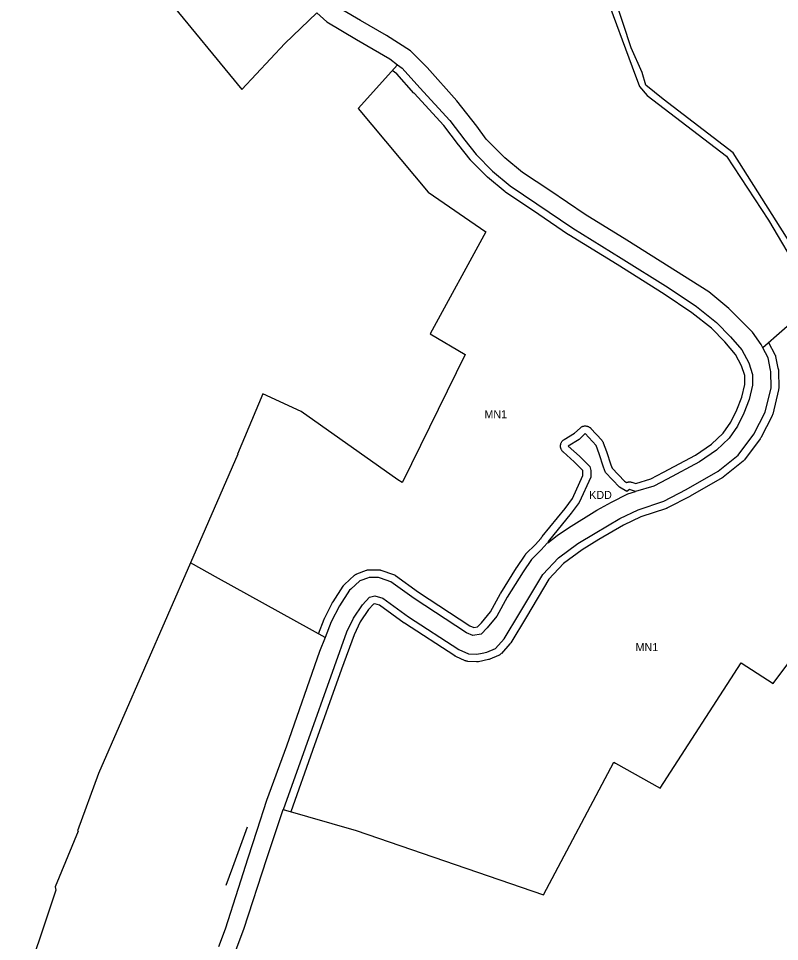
# Model space of a CAD drawing. Extents: x 7435758 to 7439981, y 5550649 to 5554049.
# Drawn here: x 7439239 to 7439733, y 5552845 to 5553445 of the extents above; entities that cross this region are included whole.
import ezdxf

# ---------------------------------------------------------------- set-up
doc = ezdxf.new("R2010")
doc.units = 0
for name, color, linetype in [('linie_rozgraniczające', 7, 'Continuous'), ('linie_zabudowy_nieprzekraczalne', 7, 'Continuous'), ('oznaczenia_przeznaczen', 7, 'Continuous')]:
    doc.layers.add(name, color=color, linetype=linetype)

msp = doc.modelspace()

# ---------------------------------------------------------------- linework, layer by layer
at = {"layer": 'linie_rozgraniczające'}
for p, q in [((7439600.88, 5553512.3), (7439637.66, 5553413.68)), ((7439301.05, 5553499.96), (7439384, 5553398.96)), ((7439636.99, 5553425.88), (7439626.65, 5553457.88)), ((7439411.84, 5553428.79), (7439432.82, 5553448.74)), ((7439432.82, 5553448.74), (7439439.32, 5553442.88)), ((7439461.17, 5553443.77), (7439449.57, 5553450.46)), ((7439439.32, 5553442.88), (7439458.54, 5553431.42)), ((7439477.97, 5553434.03), (7439461.17, 5553443.77)), ((7439384, 5553398.96), (7439411.84, 5553428.79)), ((7439458.54, 5553431.42), (7439480.15, 5553418.75)), ((7439493.49, 5553423.98), (7439477.97, 5553434.03)), ((7439504.34, 5553413.22), (7439493.49, 5553423.98)), ((7439644.02, 5553409.86), (7439636.99, 5553425.88)), ((7439480.15, 5553418.75), (7439485.04, 5553415.02)), ((7439485.04, 5553415.02), (7439459.63, 5553386.44)), ((7439485.04, 5553415.02), (7439488.08, 5553412.69)), ((7439488.08, 5553412.69), (7439499.54, 5553399.88)), ((7439523.71, 5553391.61), (7439504.34, 5553413.22)), ((7439637.66, 5553413.68), (7439642.44, 5553400.76)), ((7439646.47, 5553401.81), (7439644.02, 5553409.86)), ((7439499.54, 5553399.88), (7439519.15, 5553378.79)), ((7439642.44, 5553400.76), (7439647.28, 5553394.93)), ((7439657.82, 5553392.7), (7439646.47, 5553401.81)), ((7439647.28, 5553394.93), (7439698.84, 5553355.57)), ((7439703.19, 5553357.69), (7439657.82, 5553392.7)), ((7439536.75, 5553375.08), (7439523.71, 5553391.61)), ((7439459.63, 5553386.44), (7439505.06, 5553332.29)), ((7439519.15, 5553378.79), (7439528.79, 5553365.9)), ((7439542.82, 5553366.73), (7439536.75, 5553375.08)), ((7439528.79, 5553365.9), (7439536.2, 5553356.56)), ((7439554.78, 5553354.45), (7439542.82, 5553366.73)), ((7439748.06, 5553286.69), (7439703.19, 5553357.69)), ((7439536.2, 5553356.56), (7439546.8, 5553345.79)), ((7439566.36, 5553345.02), (7439554.78, 5553354.45)), ((7439698.84, 5553355.57), (7439726.22, 5553313.97)), ((7439546.8, 5553345.79), (7439558.26, 5553336.23)), ((7439584.03, 5553333.24), (7439566.36, 5553345.02)), ((7439558.26, 5553336.23), (7439575.65, 5553324.69)), ((7439607.06, 5553317.76), (7439584.03, 5553333.24)), ((7439505.06, 5553332.29), (7439542.61, 5553306.52)), ((7439575.65, 5553324.69), (7439598.96, 5553308.71)), ((7439634.18, 5553301.02), (7439607.06, 5553317.76)), ((7439598.96, 5553308.71), (7439630.48, 5553289.41)), ((7439726.22, 5553313.97), (7439757.05, 5553261.56)), ((7439542.61, 5553306.52), (7439506.32, 5553240.2)), ((7439687.37, 5553267.5), (7439634.18, 5553301.02)), ((7439630.48, 5553289.41), (7439661.08, 5553270.21)), ((7439661.08, 5553270.21), (7439679.29, 5553257.92)), ((7439700.31, 5553256.56), (7439687.37, 5553267.5)), ((7439757.05, 5553261.56), (7439722.38, 5553231.16)), ((7439679.29, 5553257.92), (7439692.48, 5553247.52)), ((7439715.78, 5553241.3), (7439700.31, 5553256.56)), ((7439692.48, 5553247.52), (7439701.45, 5553238.25)), ((7439506.32, 5553240.2), (7439529.01, 5553226.77)), ((7439701.45, 5553238.25), (7439708.83, 5553229.69)), ((7439721.32, 5553233.19), (7439715.78, 5553241.3)), ((7439722.38, 5553231.16), (7439721.32, 5553233.19)), ((7439725.84, 5553224.52), (7439722.38, 5553231.16)), ((7439529.01, 5553226.77), (7439488.29, 5553143.79)), ((7439708.83, 5553229.69), (7439713.34, 5553221.28)), ((7439713.34, 5553221.28), (7439715.72, 5553213.82)), ((7439727.46, 5553216.51), (7439725.84, 5553224.52)), ((7439715.72, 5553213.82), (7439715.75, 5553206.79)), ((7439727.74, 5553215.81), (7439727.46, 5553216.51)), ((7439727.8, 5553205.01), (7439727.74, 5553215.81)), ((7439715.75, 5553206.79), (7439713.65, 5553197.46)), ((7439397.71, 5553201.15), (7439381.25, 5553162.1)), ((7439422.48, 5553189.83), (7439397.71, 5553201.15)), ((7439724.05, 5553189.22), (7439727.8, 5553205.01)), ((7439713.65, 5553197.46), (7439710.1, 5553188.72)), ((7439485.25, 5553145.29), (7439422.48, 5553189.83)), ((7439716.67, 5553174.92), (7439724.05, 5553189.22)), ((7439710.1, 5553188.72), (7439706.02, 5553180.22)), ((7439706.02, 5553180.22), (7439700.6, 5553172.44)), ((7439603.12, 5553171.56), (7439596.04, 5553167.28)), ((7439607.13, 5553175.34), (7439603.12, 5553171.56)), ((7439614.15, 5553167.65), (7439607.13, 5553175.34)), ((7439700.6, 5553172.44), (7439692.33, 5553164.56)), ((7439706.52, 5553161.34), (7439716.67, 5553174.92)), ((7439596.04, 5553167.28), (7439603.38, 5553160.69)), ((7439616.19, 5553162.12), (7439614.15, 5553167.65)), ((7439381.35, 5553162.05), (7439350.6, 5553091.47)), ((7439381.25, 5553162.1), (7439381.35, 5553162.05)), ((7439603.38, 5553160.69), (7439610, 5553153.89)), ((7439619.07, 5553153.53), (7439616.19, 5553162.12)), ((7439692.33, 5553164.56), (7439681.43, 5553157.08)), ((7439693.5, 5553150.93), (7439706.52, 5553161.34)), ((7439610, 5553153.89), (7439610.64, 5553151.38)), ((7439620.3, 5553150.14), (7439619.07, 5553153.53)), ((7439681.43, 5553157.08), (7439660.27, 5553145.8)), ((7439610.64, 5553147.03), (7439603.15, 5553130.59)), ((7439610.64, 5553151.38), (7439610.64, 5553147.03)), ((7439629.39, 5553140.54), (7439620.3, 5553150.14)), ((7439672.71, 5553138.98), (7439693.5, 5553150.93)), ((7439488.18, 5553143.57), (7439485.25, 5553145.29)), ((7439488.29, 5553143.79), (7439488.18, 5553143.57)), ((7439651.6, 5553141.28), (7439639.85, 5553137.7)), ((7439660.27, 5553145.8), (7439651.6, 5553141.28)), ((7439624.15, 5553130.79), (7439634.87, 5553136.18)), ((7439634.03, 5553137.83), (7439629.39, 5553140.54)), ((7439635.8, 5553138.99), (7439634.03, 5553137.83)), ((7439634.87, 5553136.18), (7439639.85, 5553137.7)), ((7439639.85, 5553137.7), (7439635.8, 5553138.99)), ((7439658.2, 5553131.53), (7439672.71, 5553138.98)), ((7439603.15, 5553130.59), (7439597.99, 5553123.68)), ((7439614.72, 5553125.72), (7439624.15, 5553130.79)), ((7439641.41, 5553125.91), (7439658.2, 5553131.53)), ((7439597.99, 5553123.68), (7439582.97, 5553105.31)), ((7439596.31, 5553114.17), (7439614.72, 5553125.72)), ((7439629.57, 5553120.21), (7439641.41, 5553125.91)), ((7439613.49, 5553110.78), (7439629.57, 5553120.21)), ((7439588.96, 5553109.18), (7439596.31, 5553114.17)), ((7439582.76, 5553104.51), (7439588.96, 5553109.18)), ((7439582.97, 5553105.31), (7439582.76, 5553104.51)), ((7439602.24, 5553104.01), (7439613.49, 5553110.78)), ((7439578.39, 5553099.9), (7439572.13, 5553093.65)), ((7439582.38, 5553104.23), (7439578.39, 5553099.9)), ((7439582.76, 5553104.51), (7439582.38, 5553104.23)), ((7439589.72, 5553094.72), (7439602.24, 5553104.01)), ((7439572.13, 5553093.65), (7439566.73, 5553085.62)), ((7439579.46, 5553083.88), (7439589.72, 5553094.72)), ((7439350.6, 5553091.47), (7439290.94, 5552954.55)), ((7439368.93, 5553081.28), (7439350.6, 5553091.47)), ((7439438.12, 5553042.85), (7439368.93, 5553081.28)), ((7439465.69, 5553081.56), (7439461.38, 5553079.93)), ((7439466.73, 5553081.95), (7439465.69, 5553081.56)), ((7439469.44, 5553081.94), (7439466.73, 5553081.95)), ((7439472.72, 5553081.93), (7439469.44, 5553081.94)), ((7439474.12, 5553081.46), (7439472.72, 5553081.93)), ((7439480.91, 5553079.14), (7439474.12, 5553081.46)), ((7439566.73, 5553085.62), (7439556.46, 5553069.05)), ((7439564.69, 5553059), (7439579.46, 5553083.88)), ((7439460.57, 5553079.62), (7439454.83, 5553074.35)), ((7439461.38, 5553079.93), (7439460.57, 5553079.62)), ((7439495.94, 5553068.29), (7439480.91, 5553079.14)), ((7439729.26, 5553013.06), (7439776.92, 5553077.3)), ((7439454.05, 5553073.62), (7439447.43, 5553063.46)), ((7439454.83, 5553074.35), (7439454.05, 5553073.62)), ((7439462.4, 5553064.17), (7439466.87, 5553069.02)), ((7439466.87, 5553069.02), (7439470.4, 5553069.99)), ((7439470.4, 5553069.99), (7439475.67, 5553068.55)), ((7439556.46, 5553069.05), (7439549.67, 5553056.8)), ((7439447.43, 5553063.46), (7439442.12, 5553053.08)), ((7439456.58, 5553055.57), (7439462.4, 5553064.17)), ((7439475.67, 5553068.55), (7439492.35, 5553056.33)), ((7439529.92, 5553045.97), (7439495.94, 5553068.29)), ((7439554.4, 5553042.11), (7439564.69, 5553059)), ((7439442.12, 5553053.08), (7439438.12, 5553042.85)), ((7439452.27, 5553046.61), (7439456.58, 5553055.57)), ((7439492.35, 5553056.33), (7439525.04, 5553035.16)), ((7439549.67, 5553056.8), (7439543.46, 5553049.25)), ((7439444.13, 5553024.06), (7439452.27, 5553046.61)), ((7439534.15, 5553044.32), (7439529.92, 5553045.97)), ((7439539.59, 5553045.06), (7439534.15, 5553044.32)), ((7439543.46, 5553049.25), (7439539.59, 5553045.06)), ((7439438.12, 5553042.85), (7439434.57, 5553033.76)), ((7439548.89, 5553035.85), (7439554.4, 5553042.11)), ((7439434.57, 5553033.76), (7439412.96, 5552972.33)), ((7439525.04, 5553035.16), (7439531.19, 5553032.39)), ((7439540.15, 5553032.79), (7439543.22, 5553033.43)), ((7439543.22, 5553033.43), (7439548.89, 5553035.85)), ((7439531.19, 5553032.39), (7439536.69, 5553032.07)), ((7439536.69, 5553032.07), (7439540.15, 5553032.79)), ((7439425.28, 5552971.29), (7439444.13, 5553024.06)), ((7439655.72, 5552945.12), (7439708.35, 5553026.55)), ((7439708.35, 5553026.55), (7439729.26, 5553013.06)), ((7439412.96, 5552972.33), (7439399.94, 5552937.03)), ((7439410.99, 5552931.2), (7439425.28, 5552971.29)), ((7439579.94, 5552875.84), (7439625.65, 5552961.95)), ((7439625.65, 5552961.95), (7439626.78, 5552961.32)), ((7439626.78, 5552961.32), (7439655.72, 5552945.12)), ((7439290.94, 5552954.55), (7439277.23, 5552917.24)), ((7439399.94, 5552937.03), (7439393.66, 5552917.46)), ((7439400.35, 5552899.35), (7439410.95, 5552931.08)), ((7439410.95, 5552931.08), (7439410.99, 5552931.2)), ((7439410.95, 5552931.08), (7439458.23, 5552917.63)), ((7439277.61, 5552917.1), (7439262.73, 5552880.88)), ((7439277.23, 5552917.24), (7439277.61, 5552917.1)), ((7439393.66, 5552917.46), (7439387.92, 5552899.56)), ((7439458.23, 5552917.63), (7439579.94, 5552875.84)), ((7439387.92, 5552899.56), (7439381.61, 5552879.77)), ((7439385.2, 5552853.46), (7439400.35, 5552899.35)), ((7439263.21, 5552878.78), (7439255.67, 5552855.96)), ((7439262.73, 5552880.88), (7439263.21, 5552878.78)), ((7439381.61, 5552879.77), (7439373.25, 5552853.51)), ((7439255.67, 5552855.96), (7439238.89, 5552807.33)), ((7439373.25, 5552853.51), (7439368.77, 5552842.02)), ((7439372.45, 5552819.32), (7439385.2, 5552853.46))]:
    msp.add_line(p, q, dxfattribs=at)
at = {"layer": 'linie_zabudowy_nieprzekraczalne'}
for points in [[(7439433.74, 5553045.38), (7439437.46, 5553054.9), (7439437.55, 5553055.11), (7439437.67, 5553055.36), (7439442.97, 5553065.73), (7439443, 5553065.78), (7439443.16, 5553066.06), (7439443.24, 5553066.19), (7439449.86, 5553076.35), (7439449.96, 5553076.5), (7439450.16, 5553076.76), (7439450.37, 5553077.01), (7439450.6, 5553077.25), (7439450.66, 5553077.31), (7439457.19, 5553083.3), (7439457.37, 5553083.46), (7439457.63, 5553083.66), (7439457.9, 5553083.84), (7439458.18, 5553084.01), (7439458.48, 5553084.16), (7439458.78, 5553084.28), (7439458.8, 5553084.29), (7439464.96, 5553086.63), (7439465.24, 5553086.72), (7439465.56, 5553086.81), (7439465.88, 5553086.88), (7439466.2, 5553086.92), (7439466.53, 5553086.95), (7439466.75, 5553086.95), (7439472.74, 5553086.93), (7439472.85, 5553086.93), (7439473.17, 5553086.91), (7439473.5, 5553086.87), (7439473.82, 5553086.81), (7439474.14, 5553086.73), (7439474.34, 5553086.67), (7439482.52, 5553083.87), (7439482.63, 5553083.83), (7439482.94, 5553083.71), (7439483.23, 5553083.57), (7439483.52, 5553083.41), (7439483.79, 5553083.23), (7439483.84, 5553083.19), (7439498.77, 5553072.41), (7439532.23, 5553050.43), (7439534.76, 5553049.44), (7439537.14, 5553049.77), (7439539.69, 5553052.54), (7439545.52, 5553059.62), (7439552.09, 5553071.48), (7439552.2, 5553071.66), (7439552.21, 5553071.69), (7439562.48, 5553088.25), (7439562.58, 5553088.41), (7439567.99, 5553096.44), (7439568.05, 5553096.53), (7439568.24, 5553096.79), (7439568.46, 5553097.04), (7439568.6, 5553097.19), (7439574.79, 5553103.36), (7439578.36, 5553107.23), (7439578.4, 5553107.33), (7439578.54, 5553107.63), (7439578.7, 5553107.91), (7439578.88, 5553108.18), (7439579.08, 5553108.45), (7439579.1, 5553108.47), (7439594.05, 5553126.76), (7439598.82, 5553133.15), (7439605.64, 5553148.12), (7439605.64, 5553150.75), (7439605.49, 5553151.36), (7439599.91, 5553157.08), (7439592.7, 5553163.56), (7439592.65, 5553163.61), (7439592.42, 5553163.84), (7439592.2, 5553164.08), (7439592, 5553164.34), (7439591.82, 5553164.61), (7439591.65, 5553164.89), (7439591.5, 5553165.18), (7439591.38, 5553165.48), (7439591.27, 5553165.79), (7439591.18, 5553166.11), (7439591.11, 5553166.43), (7439591.07, 5553166.75), (7439591.04, 5553167.08), (7439591.04, 5553167.41), (7439591.06, 5553167.73), (7439591.1, 5553168.06), (7439591.16, 5553168.38), (7439591.24, 5553168.7), (7439591.35, 5553169.01), (7439591.47, 5553169.31), (7439591.61, 5553169.6), (7439591.77, 5553169.89), (7439591.95, 5553170.16), (7439592.15, 5553170.42), (7439592.36, 5553170.67), (7439592.59, 5553170.9), (7439592.84, 5553171.12), (7439593.1, 5553171.32), (7439593.37, 5553171.51), (7439593.46, 5553171.56), (7439600.08, 5553175.56), (7439603.7, 5553178.98), (7439603.93, 5553179.18), (7439604.19, 5553179.39), (7439604.46, 5553179.57), (7439604.74, 5553179.74), (7439605.03, 5553179.88), (7439605.33, 5553180.01), (7439605.64, 5553180.12), (7439605.96, 5553180.2), (7439606.28, 5553180.27), (7439606.6, 5553180.32), (7439606.93, 5553180.34), (7439607.26, 5553180.34), (7439607.58, 5553180.32), (7439607.91, 5553180.28), (7439608.23, 5553180.22), (7439608.55, 5553180.14), (7439608.86, 5553180.04), (7439609.16, 5553179.91), (7439609.45, 5553179.77), (7439609.74, 5553179.61), (7439610.01, 5553179.43), (7439610.27, 5553179.23), (7439610.52, 5553179.02), (7439610.75, 5553178.79), (7439610.83, 5553178.72), (7439617.84, 5553171.02), (7439617.99, 5553170.86), (7439618.19, 5553170.6), (7439618.38, 5553170.33), (7439618.54, 5553170.05), (7439618.69, 5553169.75), (7439618.82, 5553169.45), (7439618.84, 5553169.38), (7439620.88, 5553163.84), (7439620.93, 5553163.71), (7439623.8, 5553155.18), (7439624.65, 5553152.82), (7439632.53, 5553144.5), (7439633.98, 5553143.65), (7439634, 5553143.65), (7439634.31, 5553143.76), (7439634.62, 5553143.85), (7439634.94, 5553143.91), (7439635.27, 5553143.96), (7439635.59, 5553143.98), (7439635.92, 5553143.99), (7439636.25, 5553143.97), (7439636.57, 5553143.93), (7439636.89, 5553143.87), (7439637.21, 5553143.78), (7439637.22, 5553143.78), (7439637.31, 5553143.75), (7439639.88, 5553142.93), (7439649.69, 5553145.93), (7439657.94, 5553150.23), (7439678.83, 5553161.36), (7439689.17, 5553168.45), (7439696.79, 5553175.71), (7439701.68, 5553182.74), (7439705.53, 5553190.74), (7439708.86, 5553198.96), (7439710.75, 5553207.33), (7439710.73, 5553213.03), (7439708.71, 5553219.32), (7439704.68, 5553226.84), (7439697.76, 5553234.87), (7439689.12, 5553243.8), (7439676.34, 5553253.88), (7439658.35, 5553266.02), (7439627.84, 5553285.17), (7439596.35, 5553304.45), (7439596.13, 5553304.59), (7439572.86, 5553320.55), (7439555.49, 5553332.06), (7439555.37, 5553332.14), (7439555.11, 5553332.34), (7439555.05, 5553332.39), (7439543.59, 5553341.95), (7439543.41, 5553342.12), (7439543.23, 5553342.29), (7439532.64, 5553353.06), (7439532.58, 5553353.12), (7439532.36, 5553353.36), (7439532.29, 5553353.45), (7439524.88, 5553362.79), (7439524.79, 5553362.91), (7439515.31, 5553375.58), (7439495.88, 5553396.47), (7439495.82, 5553396.54), (7439484.67, 5553409.01), (7439481.64, 5553411.32)], [(7439726.25, 5553234.55), (7439730.27, 5553226.83), (7439730.37, 5553226.62), (7439730.5, 5553226.32), (7439730.61, 5553226.01), (7439730.7, 5553225.69), (7439730.74, 5553225.51), (7439732.28, 5553217.93), (7439732.39, 5553217.64), (7439732.41, 5553217.61), (7439732.51, 5553217.3), (7439732.6, 5553216.98), (7439732.67, 5553216.66), (7439732.71, 5553216.34), (7439732.74, 5553216.01), (7439732.74, 5553215.84), (7439732.8, 5553205.04), (7439732.79, 5553204.89), (7439732.78, 5553204.56), (7439732.74, 5553204.23), (7439732.67, 5553203.91), (7439732.66, 5553203.85), (7439728.91, 5553188.06), (7439728.84, 5553187.8), (7439728.74, 5553187.49), (7439728.62, 5553187.19), (7439728.49, 5553186.92), (7439721.11, 5553172.63), (7439721.1, 5553172.6), (7439720.94, 5553172.32), (7439720.76, 5553172.04), (7439720.67, 5553171.93), (7439710.52, 5553158.35), (7439710.41, 5553158.2), (7439710.19, 5553157.95), (7439709.96, 5553157.72), (7439709.72, 5553157.5), (7439709.64, 5553157.43), (7439696.62, 5553147.03), (7439696.44, 5553146.89), (7439696.17, 5553146.71), (7439695.99, 5553146.6), (7439675.21, 5553134.64), (7439675.11, 5553134.59), (7439675, 5553134.53), (7439660.48, 5553127.08), (7439660.3, 5553126.99), (7439660, 5553126.86), (7439659.79, 5553126.79), (7439643.3, 5553121.27), (7439631.92, 5553115.8), (7439616.04, 5553106.48), (7439605.02, 5553099.85), (7439593.05, 5553090.97), (7439583.47, 5553080.85), (7439568.99, 5553056.44), (7439568.96, 5553056.39), (7439568.95, 5553056.39), (7439558.67, 5553039.51), (7439558.66, 5553039.51), (7439558.48, 5553039.23), (7439558.29, 5553038.97), (7439558.15, 5553038.81), (7439552.64, 5553032.55), (7439552.56, 5553032.46), (7439552.33, 5553032.23), (7439552.09, 5553032.01), (7439551.83, 5553031.81), (7439551.56, 5553031.63), (7439551.28, 5553031.46), (7439550.99, 5553031.32), (7439550.86, 5553031.26), (7439545.19, 5553028.83), (7439545.02, 5553028.76), (7439544.71, 5553028.66), (7439544.4, 5553028.57), (7439544.25, 5553028.53), (7439537.72, 5553027.17), (7439537.55, 5553027.14), (7439537.22, 5553027.09), (7439536.9, 5553027.07), (7439536.57, 5553027.07), (7439536.4, 5553027.07), (7439530.9, 5553027.4), (7439530.74, 5553027.41), (7439530.42, 5553027.45), (7439530.1, 5553027.51), (7439529.78, 5553027.6), (7439529.47, 5553027.7), (7439529.17, 5553027.82), (7439529.14, 5553027.83), (7439522.99, 5553030.6), (7439522.72, 5553030.73), (7439522.44, 5553030.89), (7439522.33, 5553030.96), (7439489.64, 5553052.14), (7439489.47, 5553052.25), (7439489.4, 5553052.3), (7439473.46, 5553063.97), (7439470.4, 5553064.81), (7439469.57, 5553064.58), (7439466.33, 5553061.06), (7439460.92, 5553053.07), (7439456.89, 5553044.68), (7439448.84, 5553022.37), (7439429.99, 5552969.61), (7439415.77, 5552929.71)], [(7439373.83, 5552882.06), (7439378.12, 5552893.7), (7439387.79, 5552919.92)]]:
    msp.add_lwpolyline(points, dxfattribs=at)

# ---------------------------------------------------------------- texts
at = {"layer": 'oznaczenia_przeznaczen'}
for s, p in [('MN1', (7439541.61, 5553185.34)), ('KDD', (7439609.7, 5553132.92)), ('MN1', (7439639.82, 5553034.04))]:
    msp.add_text(s, height=5.2, dxfattribs=at).set_placement(p)

doc.saveas('drawing.dxf')
